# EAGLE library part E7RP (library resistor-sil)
SIL RESISTOR
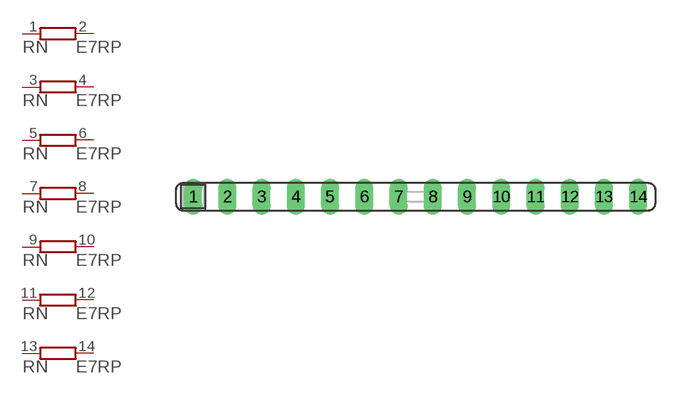
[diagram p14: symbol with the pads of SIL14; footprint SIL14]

Designator prefix RN; gates A=RPV B=RPV C=RPV D=RPV E=RPV F=RPV G=RPV

## E7RP (OC_FARNELL: unknown; OC_NEWARK: unknown)  [SIL14]
1  A:1  pas
2  A:2  pas
3  B:1  pas
4  B:2  pas
5  C:1  pas
6  C:2  pas
7  D:1  pas
8  D:2  pas
9  E:1  pas
10  E:2  pas
11  F:1  pas
12  F:2  pas
13  G:1  pas
14  G:2  pas

## Footprint SIL14 (pad centres in mm)
Single In Line
drill 0.813 long: 1 -16.51,0; 2 -13.97,0; 3 -11.43,0; 4 -8.89,0; 5 -6.35,0; 6 -3.81,0; 7 -1.27,0; 8 1.27,0; 9 3.81,0; 10 6.35,0; 11 8.89,0; 12 11.43,0; 13 13.97,0; 14 16.51,0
